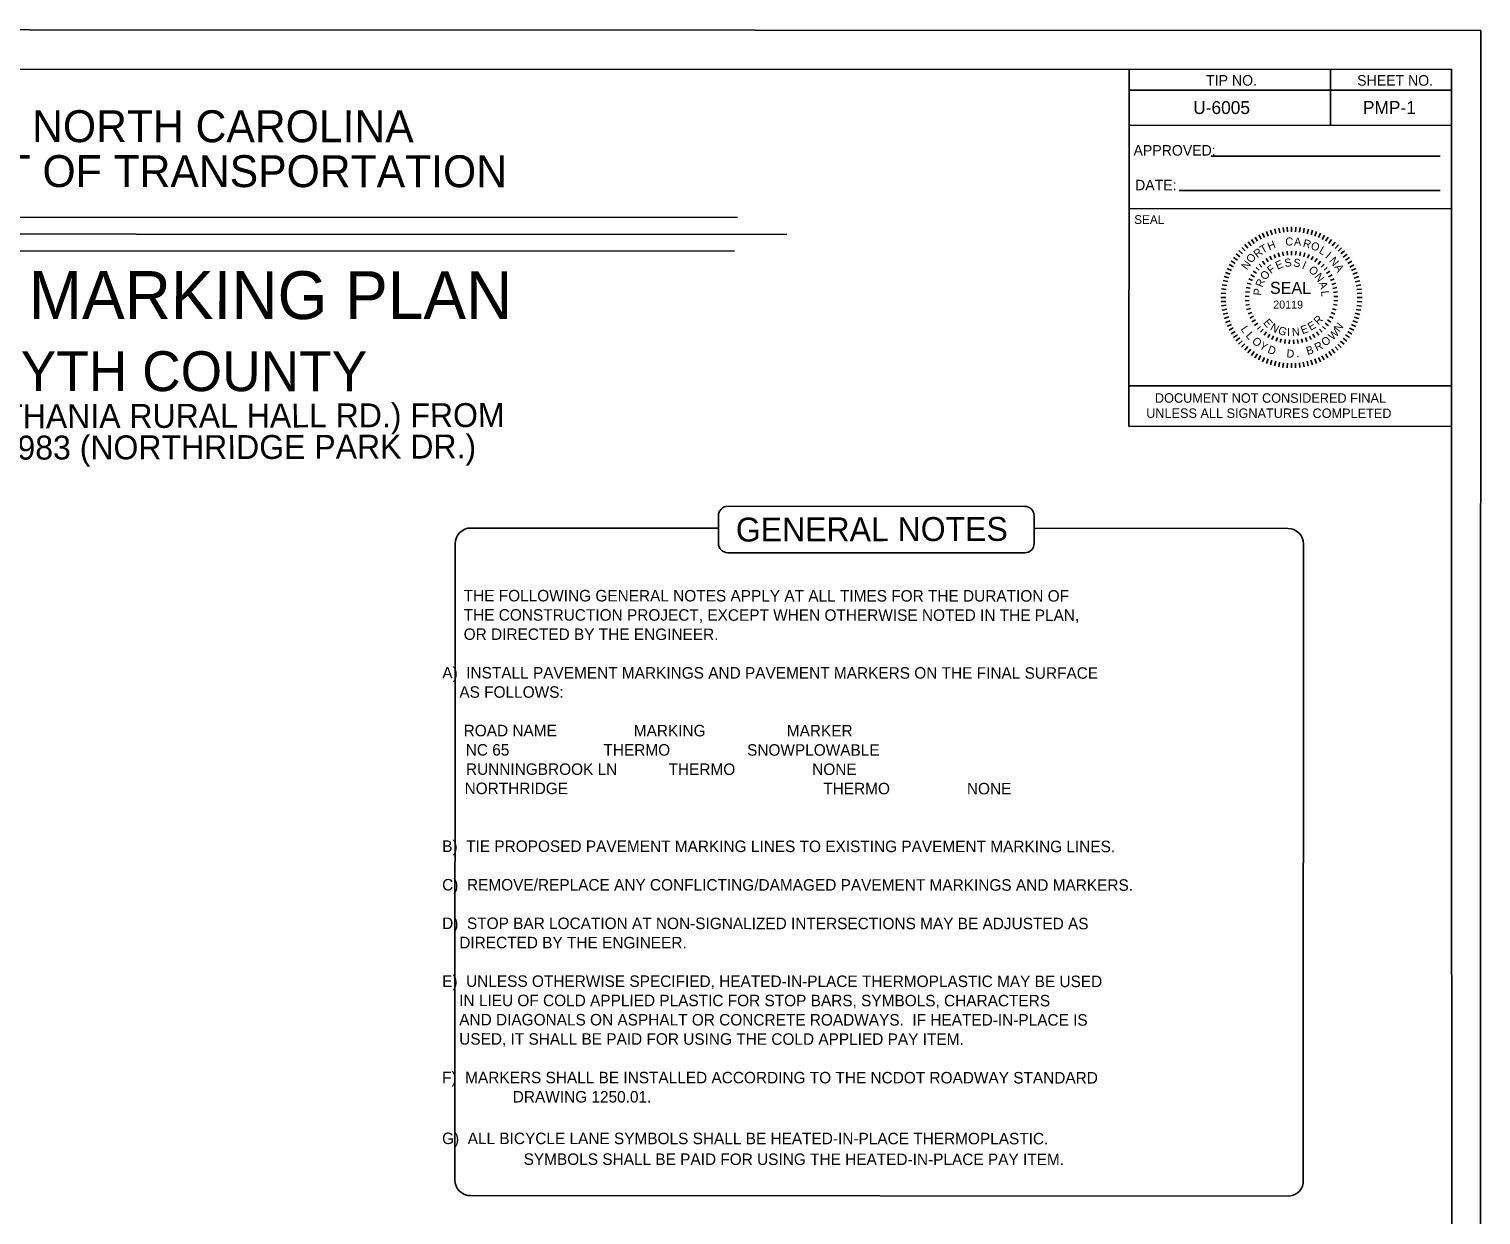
# Model space of a CAD drawing. Extents: x 50667 to 52386, y 46650 to 50479.
# Drawn here: x 51544 to 52386, y 49792 to 50479 of the extents above; entities that cross this region are included whole.
import ezdxf

# ---------------------------------------------------------------- set-up
doc = ezdxf.new("R2010")
doc.units = 0
for name, color, linetype in [('Default', 7, 'Continuous'), ('DEV TUBULAR MARKER SECTIONAL VIEW CELL', 7, 'Continuous'), ('Exist Utilities Power Pole Text Tag Number', 7, 'Continuous'), ('Exist Vertical Profile Ground Line', 7, 'Continuous'), ('Exist Vertical Profile Vertical Axis Label', 7, 'Continuous'), ('Old_Level_32', 7, 'Continuous'), ('Prop VPI Ditch Grade Left Label', 7, 'Continuous'), ('TSCONFLICT', 7, 'Continuous')]:
    doc.layers.add(name, color=color, linetype=linetype)

msp = doc.modelspace()

# ---------------------------------------------------------------- linework, layer by layer
at = {"layer": 'Default'}
for p, q in [((52257.26, 50359.9), (52258.55, 50357.43)), ((52259.49, 50360.98), (52260.62, 50358.44)), ((52261.77, 50361.92), (52262.75, 50359.31)), ((52264.1, 50362.73), (52264.92, 50360.06)), ((52266.48, 50363.38), (52267.14, 50360.68)), ((52268.9, 50363.9), (52269.39, 50361.16)), ((52271.34, 50364.26), (52271.67, 50361.5)), ((52273.79, 50364.48), (52273.96, 50361.7)), ((52276.26, 50364.56), (52276.26, 50361.77)), ((52278.73, 50364.48), (52278.56, 50361.7)), ((52281.19, 50364.25), (52280.85, 50361.49)), ((52283.63, 50363.88), (52283.13, 50361.14)), ((52286.04, 50363.36), (52285.38, 50360.65)), ((52288.42, 50362.69), (52287.59, 50360.03)), ((52290.75, 50361.88), (52289.76, 50359.28)), ((52293.03, 50360.93), (52291.89, 50358.39)), ((52295.25, 50359.85), (52293.95, 50357.38)), ((52247.35, 50352.62), (52249.31, 50350.65)), ((52249.14, 50354.31), (52250.99, 50352.23)), ((52251.05, 50355.89), (52252.76, 50353.7)), ((52253.03, 50357.35), (52254.61, 50355.06)), ((52255.11, 50358.69), (52256.55, 50356.31)), ((52297.4, 50358.63), (52295.96, 50356.25)), ((52299.47, 50357.29), (52297.89, 50355)), ((52301.46, 50355.82), (52299.74, 50353.63)), ((52303.36, 50354.24), (52301.51, 50352.16)), ((52305.15, 50352.54), (52303.18, 50350.58)), ((52240.04, 50342.73), (52242.51, 50341.43)), ((52241.26, 50344.88), (52243.64, 50343.43)), ((52242.6, 50346.95), (52244.89, 50345.36)), ((52244.07, 50348.93), (52246.26, 50347.21)), ((52245.65, 50350.83), (52247.73, 50348.98)), ((52257.42, 50342.99), (52259.04, 50341.32)), ((52259.37, 50344.71), (52260.82, 50342.89)), ((52261.47, 50346.24), (52262.74, 50344.29)), ((52263.72, 50347.55), (52264.79, 50345.5)), ((52266.08, 50348.65), (52266.95, 50346.49)), ((52268.54, 50349.51), (52269.2, 50347.28)), ((52271.07, 50350.13), (52271.51, 50347.85)), ((52273.64, 50350.5), (52273.86, 50348.19)), ((52276.25, 50350.62), (52276.24, 50348.3)), ((52276.24, 50348.3), (52276.25, 50350.62)), ((52278.85, 50350.49), (52278.62, 50348.18)), ((52281.42, 50350.11), (52280.97, 50347.83)), ((52283.95, 50349.49), (52283.28, 50347.26)), ((52286.4, 50348.62), (52285.52, 50346.47)), ((52288.76, 50347.52), (52287.68, 50345.46)), ((52291, 50346.2), (52289.73, 50344.25)), ((52293.11, 50344.66), (52291.65, 50342.85)), ((52295.05, 50342.93), (52293.43, 50341.27)), ((52306.84, 50350.75), (52304.75, 50348.9)), ((52308.42, 50348.84), (52306.22, 50347.13)), ((52309.88, 50346.86), (52307.59, 50345.28)), ((52311.22, 50344.78), (52308.83, 50343.34)), ((52237.2, 50335.9), (52239.86, 50335.07)), ((52238.01, 50338.23), (52240.61, 50337.24)), ((52238.96, 50340.51), (52241.5, 50339.36)), ((52251.52, 50334.47), (52253.65, 50333.54)), ((52252.68, 50336.81), (52254.71, 50335.67)), ((52254.06, 50339.02), (52255.96, 50337.69)), ((52255.64, 50341.08), (52257.41, 50339.58)), ((52296.82, 50341.03), (52295.05, 50339.53)), ((52298.4, 50338.96), (52296.49, 50337.64)), ((52299.77, 50336.74), (52297.74, 50335.61)), ((52300.92, 50334.41), (52298.79, 50333.48)), ((52312.43, 50342.63), (52309.96, 50341.33)), ((52313.5, 50340.4), (52310.96, 50339.27)), ((52314.45, 50338.12), (52311.84, 50337.14)), ((52315.25, 50335.79), (52312.59, 50334.96)), ((52235.41, 50326.21), (52238.19, 50326.04)), ((52235.64, 50328.67), (52238.4, 50328.33)), ((52236.01, 50331.1), (52238.75, 50330.6)), ((52236.53, 50333.52), (52239.24, 50332.85)), ((52249.47, 50326.97), (52251.77, 50326.69)), ((52249.91, 50329.53), (52252.18, 50329.03)), ((52250.6, 50332.04), (52252.81, 50331.32)), ((52301.84, 50331.97), (52299.63, 50331.26)), ((52302.52, 50329.46), (52300.25, 50328.96)), ((52302.96, 50326.89), (52300.65, 50326.62)), ((52315.91, 50333.41), (52313.2, 50332.75)), ((52316.43, 50330.99), (52313.68, 50330.5)), ((52316.79, 50328.55), (52314.03, 50328.22)), ((52317.01, 50326.09), (52314.23, 50325.93)), ((52235.33, 50323.74), (52238.12, 50323.73)), ((52235.4, 50321.27), (52238.18, 50321.43)), ((52235.63, 50318.81), (52238.39, 50319.14)), ((52249.28, 50324.37), (52251.59, 50324.31)), ((52249.33, 50321.77), (52251.65, 50321.93)), ((52249.65, 50319.18), (52251.93, 50319.57)), ((52300.48, 50319.58), (52302.77, 50319.19)), ((52303.07, 50321.69), (52300.76, 50321.86)), ((52303.14, 50324.29), (52300.82, 50324.24)), ((52316.78, 50318.7), (52314.01, 50319.04)), ((52317, 50321.16), (52314.22, 50321.33)), ((52317.08, 50323.62), (52314.3, 50323.63)), ((52235.99, 50316.37), (52238.73, 50316.87)), ((52236.51, 50313.96), (52239.21, 50314.62)), ((52237.16, 50311.57), (52239.83, 50312.4)), ((52237.97, 50309.24), (52240.58, 50310.23)), ((52250.2, 50316.64), (52252.44, 50317.24)), ((52251.01, 50314.16), (52253.18, 50314.98)), ((52252.04, 50311.78), (52254.12, 50312.8)), ((52253.3, 50309.5), (52255.28, 50310.72)), ((52299.07, 50309.44), (52297.1, 50310.66)), ((52300.34, 50311.71), (52298.26, 50312.74)), ((52301.38, 50314.09), (52299.21, 50314.92)), ((52302.19, 50316.57), (52299.95, 50317.18)), ((52314.41, 50309.13), (52311.8, 50310.13)), ((52315.22, 50311.46), (52312.55, 50312.3)), ((52315.88, 50313.85), (52313.18, 50314.51)), ((52316.4, 50316.26), (52313.67, 50316.76)), ((52238.91, 50306.96), (52241.45, 50308.1)), ((52239.99, 50304.74), (52242.46, 50306.03)), ((52241.2, 50302.58), (52243.58, 50304.02)), ((52242.54, 50300.51), (52244.83, 50302.09)), ((52254.78, 50307.35), (52256.63, 50308.76)), ((52256.46, 50305.36), (52258.16, 50306.94)), ((52258.31, 50303.54), (52259.86, 50305.28)), ((52260.34, 50301.91), (52261.71, 50303.79)), ((52262.52, 50300.48), (52263.7, 50302.48)), ((52264.82, 50299.27), (52265.8, 50301.37)), ((52287.52, 50299.24), (52286.55, 50301.34)), ((52289.83, 50300.44), (52288.66, 50302.45)), ((52292.01, 50301.87), (52290.65, 50303.74)), ((52294.05, 50303.49), (52292.51, 50305.23)), ((52295.91, 50305.31), (52294.21, 50306.89)), ((52297.59, 50307.29), (52295.75, 50308.71)), ((52309.81, 50300.41), (52307.53, 50302)), ((52311.16, 50302.48), (52308.78, 50303.93)), ((52312.38, 50304.64), (52309.91, 50305.93)), ((52313.46, 50306.86), (52310.92, 50308)), ((52244, 50298.52), (52246.19, 50300.23)), ((52245.58, 50296.62), (52247.66, 50298.46)), ((52247.27, 50294.82), (52249.24, 50296.79)), ((52249.06, 50293.12), (52250.91, 50295.21)), ((52250.96, 50291.54), (52252.67, 50293.73)), ((52252.94, 50290.07), (52254.53, 50292.36)), ((52267.23, 50298.28), (52268.01, 50300.47)), ((52270.27, 50299.79), (52269.71, 50297.53)), ((52272.28, 50297.03), (52272.62, 50299.33)), ((52274.87, 50296.77), (52274.98, 50299.09)), ((52277.47, 50296.77), (52277.36, 50299.09)), ((52280.06, 50297.02), (52279.73, 50299.32)), ((52282.62, 50297.52), (52282.06, 50299.77)), ((52285.11, 50298.26), (52284.34, 50300.45)), ((52299.38, 50290.01), (52297.8, 50292.3)), ((52301.37, 50291.47), (52299.66, 50293.66)), ((52303.27, 50293.05), (52301.43, 50295.14)), ((52305.07, 50294.74), (52303.1, 50296.71)), ((52306.76, 50296.53), (52304.68, 50298.38)), ((52308.35, 50298.43), (52306.16, 50300.15)), ((52255.01, 50288.73), (52256.46, 50291.11)), ((52257.16, 50287.51), (52258.46, 50289.98)), ((52259.38, 50286.43), (52260.53, 50288.97)), ((52261.66, 50285.48), (52262.65, 50288.09)), ((52263.99, 50284.67), (52264.82, 50287.34)), ((52266.37, 50284.01), (52267.04, 50286.71)), ((52268.78, 50283.48), (52269.29, 50286.22)), ((52271.22, 50283.11), (52271.56, 50285.88)), ((52273.68, 50282.88), (52273.85, 50285.66)), ((52276.15, 50282.81), (52276.15, 50285.59)), ((52278.62, 50282.88), (52278.46, 50285.66)), ((52281.08, 50283.1), (52280.75, 50285.86)), ((52283.52, 50283.46), (52283.02, 50286.2)), ((52285.93, 50283.98), (52285.27, 50286.68)), ((52288.32, 50284.64), (52287.49, 50287.3)), ((52290.65, 50285.44), (52289.66, 50288.05)), ((52292.93, 50286.39), (52291.79, 50288.93)), ((52295.15, 50287.46), (52293.86, 50289.93)), ((52297.31, 50288.67), (52295.87, 50291.06))]:
    msp.add_line(p, q, dxfattribs=at)
for points in [[(51261.15, 50370.27), (51954.95, 50369.95)], [(51229.19, 50360.53), (51983.6, 50360.18)], [(51259.46, 50350.77), (51953.26, 50350.44)]]:
    msp.add_lwpolyline(points, dxfattribs=at)
at = {"layer": 'DEV TUBULAR MARKER SECTIONAL VIEW CELL'}
msp.add_lwpolyline([(52369.04, 50455.98), (50869.05, 50455.87), (50869.12, 49405.87), (52369.12, 49405.98)], close=True, dxfattribs=at)
at = {"layer": 'Exist Utilities Power Pole Text Tag Number'}
msp.add_lwpolyline([(52386.04, 50478.48), (50703.13, 50479.27), (50702.62, 49383.36), (52385.53, 49382.58)], close=True, dxfattribs=at)
at = {"layer": 'Exist Vertical Profile Ground Line'}
for p, q in [((52298.79, 50423.48), (52298.81, 50456.02)), ((52298.8, 50431.06), (52298.81, 50456.02)), ((52369.04, 50455.98), (52369.04, 50455.98)), ((52182.05, 50443.86), (52298.8, 50443.8)), ((52298.8, 50443.8), (52369.04, 50443.76)), ((52182.04, 50423.55), (52369.03, 50423.44)), ((52229.72, 50405.64), (52362.34, 50405.58)), ((52211.03, 50385.74), (52362.33, 50385.67))]:
    msp.add_line(p, q, dxfattribs=at)
at = {"layer": 'Old_Level_32'}
msp.add_lwpolyline([(52181.97, 50272.54), (52368.96, 50272.46), (52368.95, 50248.96), (52181.96, 50249.05)], close=True, dxfattribs=at)
at = {"layer": 'Prop VPI Ditch Grade Left Label'}
msp.add_line((52386.04, 50478.48), (52386.04, 50478.48), dxfattribs=at)
at = {"layer": 'TSCONFLICT'}
for p, q in [((52182.04, 50431.12), (52182.06, 50456.07)), ((52182.02, 50383.94), (52182.04, 50431.12)), ((52181.97, 50272.54), (52182.02, 50383.94)), ((52182.02, 50375.2), (52369.01, 50375.11)), ((52368.96, 50272.46), (52181.97, 50272.54)), ((51943.96, 50181.21), (51943.97, 50197.23)), ((52126.99, 50181.12), (52127, 50197.15)), ((51800.48, 50190.07), (51943.96, 50190)), ((52127, 50189.92), (52274.1, 50189.85)), ((51791.22, 49812.2), (51791.39, 50180.98)), ((52283.01, 49811.04), (52283.18, 50180.76)), ((51800.31, 49803.1), (52274.84, 49802.88))]:
    msp.add_line(p, q, dxfattribs=at)
for points in [[(51949.42, 50202.68), (52121.55, 50202.6)], [(51949.41, 50175.75), (52121.54, 50175.67)]]:
    msp.add_lwpolyline(points, dxfattribs=at)
for centre, radius, start, end in [((51949.42, 50197.23), 5.45, 89.97341, 179.97341), ((52121.55, 50197.15), 5.45, 359.97341, 89.97341), ((51800.48, 50180.98), 9.09, 89.97341, 179.97341), ((52274.09, 50180.76), 9.09, 359.97341, 89.97341), ((51949.41, 50181.21), 5.45, 179.97341, 269.97341), ((52121.54, 50181.13), 5.45, 269.97341, 359.97341), ((51800.31, 49812.19), 9.09, 179.97341, 269.97341), ((52274.38, 49811.51), 8.64, 273.04586, 3.04586)]:
    msp.add_arc(centre, radius, start, end, dxfattribs=at)

# ---------------------------------------------------------------- texts
at = {"layer": 'Default'}
for s, height, rotation, p in [('STATE OF NORTH CAROLINA', 18.4936, 359.97341, (51418.32, 50413.79)), ('DEPARTMENT OF TRANSPORTATION', 18.4936, 359.97341, (51374.88, 50387.78)), ('R', 4.64, 38.58096, (52256.44, 50346.35)), ('T', 4.64, 30.41999, (52259.56, 50348.94)), ('H', 4.64, 20.98805, (52263.3, 50350.96)), ('C', 4.64, 357.27736, (52272.54, 50353.92)), ('A', 4.64, 357.27736, (52277.61, 50353.82)), ('R', 4.64, 345.26805, (52282.52, 50353.13)), ('O', 4.64, 342.21124, (52287.02, 50351.79)), ('L', 4.64, 329.07495, (52291.73, 50349.72)), ('N', 4.64, 53.59712, (52250.4, 50339.31)), ('O', 4.64, 51.63769, (52253.07, 50343.23)), ('F', 4.64, 38.16101, (52264.33, 50337.12)), ('E', 4.64, 22.86476, (52268.04, 50339.74)), ('S', 4.64, 7.56852, (52272.4, 50341.33)), ('S', 4.64, 352.27227, (52277.04, 50341.71)), ('I', 4.64, 336.97602, (52281.97, 50340.7)), ('I', 4.64, 319.49948, (52295.47, 50347.02)), ('N', 4.64, 310.20502, (52297.79, 50344.83)), ('PAVEMENT MARKING PLAN', 27.7403, 359.97341, (51329.78, 50311.35)), ('R', 4.64, 68.7535, (52259.4, 50329.22)), ('O', 4.64, 53.45725, (52261.24, 50333.38)), ('O', 4.64, 321.67978, (52285.71, 50338.89)), ('N', 4.64, 306.38353, (52289.28, 50335.77)), ('A', 4.64, 300.43749, (52300.85, 50341.4)), ('P', 4.64, 84.04975, (52258.69, 50324.62)), ('SEAL', 6.965, 359.92039, (52263.73, 50325.79)), ('A', 4.64, 291.08729, (52291.82, 50331.97)), ('L', 4.64, 275.79104, (52293.31, 50327.38)), ('20119', 4.64, 359.92039, (52265.62, 50317.25)), ('E', 4.64, 309.99048, (52259.56, 50308.97)), ('E', 4.64, 30.7142, (52287.3, 50304.26)), ('R', 4.64, 44.48528, (52291.73, 50307.49)), ('N', 4.64, 52.12745, (52303.94, 50303.28)), ('L', 4.64, 303.85541, (52246.51, 50305.35)), ('L', 4.64, 311.92722, (52249.38, 50301.36)), ('N', 4.64, 330.84556, (52263.45, 50305.1)), ('G', 4.64, 339.61179, (52267.99, 50302.91)), ('I', 4.64, 357.70659, (52273.51, 50301.42)), ('N', 4.64, 5.33625, (52276.66, 50301.26)), ('E', 4.64, 20.72832, (52282.54, 50302.29)), ('O', 4.64, 34.36219, (52295.47, 50295.14)), ('W', 4.64, 43.24482, (52300.04, 50298.62)), ('FORSYTH COUNTY', 23.1165, 359.97341, (51453.61, 50269.48)), ('O', 4.64, 320.56997, (52252.9, 50297.7)), ('Y', 4.64, 329.24256, (52257.11, 50294.46)), ('D', 4.64, 338.21504, (52261.94, 50291.83)), ('D', 4.64, 356.01035, (52273.22, 50288.99)), ('B', 4.64, 16.53701, (52285.5, 50290.27)), ('R', 4.64, 25.53957, (52290.86, 50292.38)), ('.', 4.64, 3.75269, (52279.07, 50288.94)), ('LOCATION: NC 65 (BETHANIA RURAL HALL RD.) FROM', 13.8702, 0.15565, (51335.63, 50247.33)), ('ANGUS ST. TO SR 3983 (NORTHRIDGE PARK DR.)', 13.8702, 0.15565, (51360.38, 50229.21)), ('GENERAL NOTES', 13.8661, 0.15565, (51954.12, 50182.21)), ('            THE FOLLOWING GENERAL NOTES APPLY AT ALL TIMES FOR THE DURATION OF', 6.6709, 359.97341, (51766.58, 50147.56)), ('            THE CONSTRUCTION PROJECT, EXCEPT WHEN OTHERWISE NOTED IN THE PLAN,', 6.6709, 359.97341, (51766.58, 50136.39)), ('            OR DIRECTED BY THE ENGINEER.', 6.6709, 359.97341, (51766.57, 50125.22)), ('       A)  INSTALL PAVEMENT MARKINGS AND PAVEMENT MARKERS ON THE FINAL SURFACE', 6.6709, 359.97341, (51766.56, 50102.87)), ('           AS FOLLOWS:', 6.6709, 359.97341, (51766.55, 50091.7)), ('            ROAD NAME                  MARKING                   MARKER            ', 6.6709, 359.97341, (51766.54, 50069.36)), ('             NC 65                      THERMO                  SNOWPLOWABLE             ', 6.6709, 359.97341, (51765.29, 50058.19)), ('             RUNNINGBROOK LN            THERMO                  NONE', 6.6709, 359.97341, (51765.39, 50047.02)), ('             NORTHRIDGE            ', 6.6709, 359.97341, (51764.62, 50035.85)), ('THERMO                  NONE', 6.6709, 359.97341, (52004.77, 50035.74)), ('       B)  TIE PROPOSED PAVEMENT MARKING LINES TO EXISTING PAVEMENT MARKING LINES.', 6.6709, 359.97341, (51766.51, 50002.34)), ('       C)  REMOVE/REPLACE ANY CONFLICTING/DAMAGED PAVEMENT MARKINGS AND MARKERS.', 6.6709, 359.97341, (51766.5, 49979.99)), ('       D)  STOP BAR LOCATION AT NON-SIGNALIZED INTERSECTIONS MAY BE ADJUSTED AS ', 6.6709, 359.97341, (51766.49, 49957.65)), ('           DIRECTED BY THE ENGINEER.', 6.6709, 359.97341, (51766.49, 49946.48)), ('       E)  UNLESS OTHERWISE SPECIFIED, HEATED-IN-PLACE THERMOPLASTIC MAY BE USED', 6.6709, 359.97341, (51766.48, 49924.14)), ('           IN LIEU OF COLD APPLIED PLASTIC FOR STOP BARS, SYMBOLS, CHARACTERS ', 6.6709, 359.97341, (51766.47, 49912.97)), ('           AND DIAGONALS ON ASPHALT OR CONCRETE ROADWAYS.  IF HEATED-IN-PLACE IS', 6.6709, 359.97341, (51766.47, 49901.8)), ('           USED, IT SHALL BE PAID FOR USING THE COLD APPLIED PAY ITEM.', 6.6709, 359.97341, (51766.46, 49890.63)), ('       F)  MARKERS SHALL BE INSTALLED ACCORDING TO THE NCDOT ROADWAY STANDARD', 6.6709, 359.97341, (51766.45, 49868.28)), ('  DRAWING 1250.01.', 6.6709, 359.97341, (51819.81, 49857.09)), ('       G)  ALL BICYCLE LANE SYMBOLS SHALL BE HEATED-IN-PLACE THERMOPLASTIC.', 6.6709, 359.97341, (51766.43, 49833)), ('SYMBOLS SHALL BE PAID FOR USING THE HEATED-IN-PLACE PAY ITEM.', 6.6709, 359.97341, (51831.06, 49820.94))]:
    msp.add_text(s, height=height, rotation=rotation, dxfattribs=at).set_placement(p)
at = {"layer": 'Exist Vertical Profile Ground Line'}
for s, height, p in [('TIP NO.', 6.11, (52226.7, 50446.51)), ('SHEET NO.', 6.11, (52314.26, 50446.46)), ('SEAL', 5.094, (52185.04, 50366.29))]:
    msp.add_text(s, height=height, rotation=359.96835, dxfattribs=at).set_placement(p)
at = {"layer": 'Exist Vertical Profile Vertical Axis Label'}
for s, p in [('APPROVED:', (52184.62, 50405.93)), ('DATE:', (52185.53, 50385.79))]:
    msp.add_text(s, height=6.11, rotation=359.96835, dxfattribs=at).set_placement(p)
at = {"layer": 'Old_Level_32'}
for s, p in [('DOCUMENT NOT CONSIDERED FINAL', (52197.04, 50262.69)), ('UNLESS ALL SIGNATURES COMPLETED', (52191.97, 50253.89))]:
    msp.add_text(s, height=5.4984, rotation=359.97341, dxfattribs=at).set_placement(p)
at = {"layer": 'TSCONFLICT'}
for s, p in [('U-6005', (52219.25, 50430.02)), ('PMP-1', (52317.62, 50430.05))]:
    msp.add_text(s, height=7.5, rotation=359.96835, dxfattribs=at).set_placement(p)

doc.saveas('drawing.dxf')
